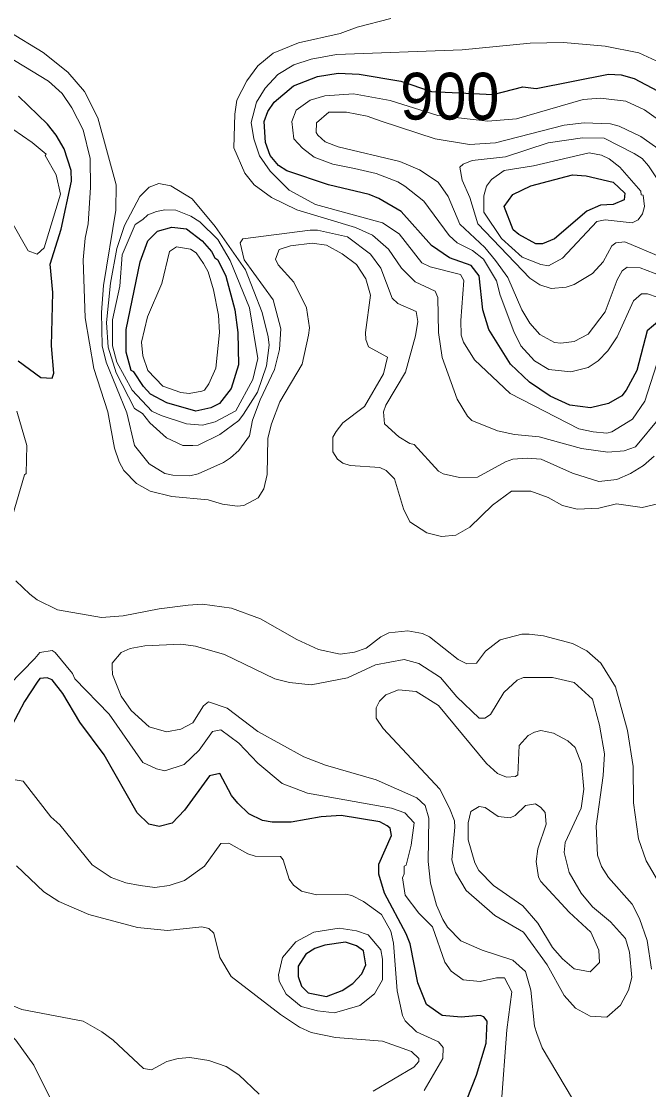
# Model space of a CAD drawing. Extents: x 423 to 448.8, y 7456.3 to 7484.
# Drawn here: x 425.114 to 426.187, y 7462.195 to 7464.022 of the extents above; entities that cross this region are included whole.
import ezdxf
from ezdxf.enums import TextEntityAlignment as Align

# ---------------------------------------------------------------- set-up
doc = ezdxf.new("R2010")
doc.units = 0
doc.header["$LTSCALE"] = 0.032
doc.layers.add('1', color=7, linetype='Continuous', lineweight=25)
doc.layers.add('2', color=7, linetype='Continuous', lineweight=13)
doc.layers.add('61', color=7, linetype='Continuous')

msp = doc.modelspace()

# ---------------------------------------------------------------- linework, layer by layer
at = {"layer": '1'}
for points in [[(426.206, 7463.5108), (426.1844, 7463.4923), (426.1666, 7463.425), (426.1488, 7463.3909), (426.1411, 7463.3816), (426.1186, 7463.3685), (426.0877, 7463.3608), (426.0521, 7463.3654), (426.0188, 7463.3809), (425.9833, 7463.4049), (425.9508, 7463.4358), (425.9136, 7463.4946), (425.9036, 7463.5286), (425.8974, 7463.5866), (425.8835, 7463.6044), (425.8464, 7463.6176), (425.8154, 7463.6384), (425.7636, 7463.6965), (425.7257, 7463.7189), (425.7087, 7463.7258), (425.6391, 7463.7421), (425.5679, 7463.7661), (425.554, 7463.7753), (425.5393, 7463.7924), (425.5315, 7463.8148), (425.5293, 7463.8504), (425.5354, 7463.8674), (425.5462, 7463.8836), (425.5795, 7463.9115), (425.6205, 7463.9277), (425.6561, 7463.9331), (425.6917, 7463.9316), (425.7629, 7463.9192), (425.8158, 7463.9015), (425.9213, 7463.8967), (425.972, 7463.9097), (425.9949, 7463.9068), (426.1186, 7463.9316), (426.1403, 7463.93), (426.162, 7463.9238), (426.2022, 7463.903)], [(425.1085, 7463.4412), (425.1472, 7463.4126), (425.1665, 7463.4118), (425.1696, 7463.4204), (425.1657, 7463.4668), (425.168, 7463.558), (425.1635, 7463.6064), (425.1821, 7463.6665), (425.1997, 7463.7483), (425.199, 7463.7669), (425.1874, 7463.804), (425.1735, 7463.8272), (425.1588, 7463.8457), (425.1092, 7463.8937)], [(425.3722, 7462.6507), (425.3498, 7462.6453), (425.332, 7462.6492), (425.3119, 7462.6686), (425.2554, 7462.7676), (425.2137, 7462.8232), (425.185, 7462.8727), (425.1665, 7462.8959), (425.158, 7462.899), (425.1456, 7462.8983), (425.141, 7462.8921), (425.1193, 7462.8588), (425.0752, 7462.7768)], [(425.8765, 7462.1797), (425.8928, 7462.2199), (425.909, 7462.2748), (425.9106, 7462.312), (425.9051, 7462.3197), (425.899, 7462.322), (425.8665, 7462.3189), (425.834, 7462.322), (425.8069, 7462.3406), (425.7922, 7462.3777), (425.7791, 7462.4443), (425.7721, 7462.4613), (425.735, 7462.5309), (425.7257, 7462.5634), (425.7257, 7462.5804), (425.7474, 7462.6299), (425.745, 7462.6422), (425.7396, 7462.6461), (425.7273, 7462.6531), (425.6608, 7462.6639), (425.6267, 7462.6616), (425.5757, 7462.6523), (425.5432, 7462.6523), (425.5262, 7462.6554), (425.5029, 7462.667), (425.4844, 7462.6848), (425.4735, 7462.6979), (425.4535, 7462.7358), (425.4356, 7462.7319), (425.3931, 7462.6731), (425.3722, 7462.6507)]]:
    msp.add_lwpolyline(points, dxfattribs=at)
for points in [[(425.9856, 7463.7405), (426.0568, 7463.7591), (426.08, 7463.7576), (426.1264, 7463.7467), (426.1465, 7463.7282), (426.1449, 7463.7166), (426.1264, 7463.7088), (426.1047, 7463.7073), (426.0815, 7463.6972), (426.0258, 7463.65), (426.0057, 7463.6415), (425.9941, 7463.6415), (425.9647, 7463.657), (425.9554, 7463.6655), (425.94, 7463.705), (425.9547, 7463.7258)], [(425.3305, 7463.6462), (425.3467, 7463.6632), (425.3715, 7463.6701), (425.3962, 7463.6671), (425.4233, 7463.6462), (425.4395, 7463.6284), (425.4449, 7463.6176), (425.4503, 7463.6137), (425.4635, 7463.5859), (425.479, 7463.5286), (425.4844, 7463.49), (425.4852, 7463.4343), (425.4728, 7463.3941), (425.4527, 7463.3685), (425.438, 7463.3608), (425.4125, 7463.3554), (425.3629, 7463.3693), (425.3351, 7463.384), (425.3227, 7463.3971), (425.3065, 7463.4227), (425.3018, 7463.425), (425.2933, 7463.4559), (425.2933, 7463.4946), (425.3173, 7463.6106)], [(425.663, 7462.3645), (425.6808, 7462.3769), (425.6963, 7462.3932), (425.7033, 7462.4086), (425.6994, 7462.4326), (425.687, 7462.4412), (425.6685, 7462.4473), (425.6329, 7462.4419), (425.6159, 7462.4365), (425.6004, 7462.4265), (425.5873, 7462.4063), (425.5872, 7462.3886), (425.5934, 7462.3723), (425.6043, 7462.3607), (425.636, 7462.3545)]]:
    msp.add_lwpolyline(points, close=True, dxfattribs=at)
at = {"layer": '2'}
for points in [[(425.7458, 7464.0267), (425.6886, 7464.012)], [(425.0914, 7464.0051), (425.151, 7463.9687), (425.1935, 7463.9347), (425.2222, 7463.9015), (425.2446, 7463.8566), (425.2763, 7463.7421), (425.2755, 7463.6988), (425.2546, 7463.5699), (425.2508, 7463.524), (425.2524, 7463.4668), (425.2593, 7463.4389), (425.2941, 7463.3523), (425.3073, 7463.2966), (425.3328, 7463.2649), (425.3591, 7463.2486), (425.373, 7463.2455), (425.4024, 7463.2447), (425.4163, 7463.2478), (425.4597, 7463.2672), (425.472, 7463.2757), (425.4859, 7463.2881), (425.5045, 7463.3128), (425.5095, 7463.3396), (425.5222, 7463.3748), (425.547, 7463.4265), (425.5555, 7463.4606), (425.5579, 7463.4962), (425.5445, 7463.5457), (425.495, 7463.6139), (425.4882, 7463.6431), (425.4929, 7463.6501), (425.6082, 7463.6647), (425.6205, 7463.6647), (425.6716, 7463.6531), (425.711, 7463.6238), (425.7288, 7463.5998), (425.7481, 7463.5487), (425.7582, 7463.5394), (425.7891, 7463.5255), (425.7922, 7463.5085), (425.7883, 7463.4838), (425.7713, 7463.4219), (425.7373, 7463.3654), (425.7334, 7463.3538), (425.735, 7463.3337), (425.7598, 7463.3113), (425.7783, 7463.2997), (425.786, 7463.2981), (425.8278, 7463.2525), (425.8356, 7463.2478)], [(425.6886, 7464.012), (425.6592, 7464.0012), (425.588, 7463.9849), (425.5447, 7463.9672), (425.5184, 7463.9455), (425.4999, 7463.92), (425.4828, 7463.8867), (425.479, 7463.8628), (425.4774, 7463.8055), (425.496, 7463.7622), (425.5122, 7463.7421), (425.5416, 7463.7204), (425.585, 7463.6996), (425.6855, 7463.6694), (425.7149, 7463.6562), (425.742, 7463.6323), (425.7644, 7463.5998), (425.7876, 7463.5766), (425.8216, 7463.5603), (425.8262, 7463.5495), (425.8278, 7463.49), (425.834, 7463.4467), (425.8595, 7463.3755), (425.8773, 7463.3469), (425.8843, 7463.3391), (425.9284, 7463.3213), (425.9578, 7463.3151), (425.9995, 7463.3113), (426.0722, 7463.2912), (426.1171, 7463.285), (426.1449, 7463.2873), (426.1643, 7463.2943), (426.206, 7463.3446)], [(426.2006, 7463.4343), (426.1805, 7463.3724), (426.1596, 7463.3414), (426.124, 7463.3198), (426.1155, 7463.3175), (426.0923, 7463.3198), (426.0676, 7463.3252), (425.95, 7463.3855), (425.8889, 7463.4428), (425.8703, 7463.473), (425.8665, 7463.4853), (425.8657, 7463.5101), (425.8711, 7463.5789), (425.8649, 7463.589), (425.8131, 7463.6021), (425.7992, 7463.609), (425.7605, 7463.6586), (425.7319, 7463.6771), (425.6174, 7463.7088), (425.5718, 7463.7328), (425.5393, 7463.7653), (425.5215, 7463.7916), (425.5115, 7463.821), (425.5068, 7463.8489), (425.5161, 7463.8836), (425.5308, 7463.9076), (425.5525, 7463.9308), (425.5803, 7463.9471), (425.6097, 7463.9571), (425.653, 7463.9649), (425.868, 7463.9733), (425.9841, 7463.9842), (426.0413, 7463.9857), (426.1125, 7463.9795), (426.1704, 7463.968), (426.2145, 7463.9471)], [(425.6113, 7463.6423), (425.5741, 7463.6377), (425.5548, 7463.6315), (425.5486, 7463.6153), (425.5532, 7463.6052), (425.5803, 7463.5758), (425.602, 7463.5317), (425.6066, 7463.4977), (425.6051, 7463.4853), (425.5942, 7463.4358), (425.5563, 7463.3709), (425.5416, 7463.3337), (425.5354, 7463.309), (425.5346, 7463.2471), (425.5285, 7463.2224), (425.5192, 7463.2068), (425.4944, 7463.1937), (425.4829, 7463.1929), (425.4581, 7463.196), (425.4334, 7463.2037), (425.3715, 7463.2092), (425.3344, 7463.2185), (425.3111, 7463.2316), (425.2895, 7463.254), (425.281, 7463.2687), (425.2732, 7463.292), (425.2662, 7463.3291), (425.2616, 7463.3538), (425.2377, 7463.4281), (425.223, 7463.5147), (425.2199, 7463.6137), (425.2229, 7463.6508), (425.2284, 7463.6756), (425.2322, 7463.7375), (425.2315, 7463.787), (425.2198, 7463.8365), (425.2005, 7463.8736), (425.1835, 7463.8984), (425.1603, 7463.9192), (425.0752, 7463.971)], [(426.2501, 7463.8202), (426.1797, 7463.8705), (426.148, 7463.8852), (426.1047, 7463.8906), (426.0753, 7463.8883), (425.9609, 7463.855), (425.9121, 7463.8512), (425.8265, 7463.861), (425.7447, 7463.8865), (425.6824, 7463.8976), (425.6329, 7463.8945), (425.6082, 7463.8867), (425.5842, 7463.8697), (425.5764, 7463.8504), (425.5803, 7463.821), (425.595, 7463.8047), (425.6151, 7463.7893), (425.6468, 7463.7777), (425.684, 7463.7699), (425.7211, 7463.7614), (425.7582, 7463.7475), (425.7698, 7463.7398), (425.8023, 7463.7142), (425.8456, 7463.6554), (425.8595, 7463.6431), (425.8858, 7463.63), (425.9044, 7463.6152), (425.9268, 7463.5781), (425.933, 7463.5534), (425.9562, 7463.4915), (425.9686, 7463.4668), (425.9918, 7463.4412), (426.0165, 7463.4265), (426.0537, 7463.4227), (426.0838, 7463.4296), (426.1008, 7463.4412), (426.117, 7463.4582), (426.1333, 7463.4822), (426.1612, 7463.5441), (426.1751, 7463.5557), (426.1852, 7463.5557), (426.2347, 7463.5387)], [(425.0659, 7463.8604), (425.1325, 7463.8148), (425.1564, 7463.7947), (425.1546, 7463.7923), (425.1734, 7463.7593), (425.1809, 7463.7263), (425.1531, 7463.6347), (425.1411, 7463.6235), (425.1253, 7463.6295), (425.0953, 7463.6825)], [(426.2084, 7463.8001), (426.1735, 7463.8248), (426.1364, 7463.8426), (426.1217, 7463.8465), (426.0769, 7463.8481), (426.0428, 7463.8442), (425.9253, 7463.814), (425.8804, 7463.8109), (425.8216, 7463.821), (425.7296, 7463.8511), (425.7056, 7463.8597), (425.67, 7463.8666), (425.6398, 7463.8666), (425.6189, 7463.8481), (425.6182, 7463.8318), (425.6213, 7463.8272), (425.6337, 7463.8156), (425.6561, 7463.807), (425.7613, 7463.7823), (425.7953, 7463.7676), (425.827, 7463.7467), (425.8441, 7463.722), (425.8642, 7463.6748), (425.9067, 7463.6353), (425.9252, 7463.6129), (425.9461, 7463.5835), (425.9701, 7463.5286), (425.984, 7463.5054), (426.001, 7463.4861), (426.0258, 7463.4729), (426.0367, 7463.4714), (426.0599, 7463.4745), (426.0838, 7463.4868), (426.1124, 7463.5248), (426.1333, 7463.5797), (426.1418, 7463.5951), (426.1503, 7463.6013), (426.1728, 7463.6005), (426.2084, 7463.5866)], [(426.2084, 7463.6183), (426.1465, 7463.6446), (426.131, 7463.6431), (426.124, 7463.6377), (426.1093, 7463.6106), (426.0908, 7463.5905), (426.0599, 7463.5719), (426.0459, 7463.5673), (426.0204, 7463.565), (426.0011, 7463.5712), (425.984, 7463.5827), (425.8951, 7463.6756), (425.8812, 7463.7205), (425.868, 7463.7499), (425.8642, 7463.7723), (425.8696, 7463.7776), (425.8851, 7463.7838), (425.9423, 7463.79), (426.015, 7463.814), (426.0738, 7463.8225), (426.1109, 7463.8218), (426.162, 7463.7955), (426.1759, 7463.787), (426.1867, 7463.7746), (426.2385, 7463.6973)], [(426.2122, 7463.1991), (426.1759, 7463.1906), (426.1318, 7463.1968), (426.1016, 7463.1891), (426.0645, 7463.1875), (426.0397, 7463.1937), (426.015, 7463.2076), (425.9856, 7463.2185), (425.9523, 7463.2185), (425.9198, 7463.1945), (425.8812, 7463.1566), (425.8572, 7463.1434), (425.8325, 7463.1411), (425.8077, 7463.1473), (425.7783, 7463.1659), (425.7675, 7463.1883), (425.752, 7463.2394), (425.7381, 7463.254), (425.7273, 7463.2587), (425.6762, 7463.2625), (425.6638, 7463.2664), (425.6546, 7463.2734), (425.6468, 7463.2858), (425.6468, 7463.3105), (425.6522, 7463.3206), (425.6638, 7463.3352), (425.7009, 7463.3631), (425.7334, 7463.4188), (425.7404, 7463.4474), (425.7079, 7463.4652), (425.7033, 7463.4776), (425.7025, 7463.49), (425.711, 7463.5534), (425.7033, 7463.5812), (425.687, 7463.606), (425.663, 7463.6245), (425.636, 7463.6392), (425.6113, 7463.6423)], [(425.1062, 7463.3554), (425.1232, 7463.2966), (425.1224, 7463.2486), (425.1193, 7463.2463), (425.0922, 7463.1527)], [(425.8356, 7463.2478), (425.8634, 7463.2417), (425.8943, 7463.2424), (425.9423, 7463.2687), (425.9547, 7463.2734), (425.9794, 7463.2749), (426.0034, 7463.2734), (426.0568, 7463.2494), (426.1016, 7463.2347), (426.1326, 7463.2386), (426.1558, 7463.2486), (426.1782, 7463.2625), (426.1967, 7463.278)], [(425.1046, 7463.0653), (425.1286, 7463.0421), (425.1409, 7463.0328), (425.1758, 7463.0158), (425.2508, 7463.0026), (425.2879, 7463.005), (425.3498, 7463.0174), (425.3993, 7463.0235), (425.4241, 7463.0251), (425.4736, 7463.0182), (425.5231, 7463.0003), (425.585, 7462.9648), (425.6221, 7462.9477), (425.6592, 7462.94), (425.684, 7462.9431), (425.704, 7462.9501), (425.7288, 7462.9694), (425.7427, 7462.9764), (425.7752, 7462.9794), (425.8, 7462.9748), (425.8124, 7462.9694), (425.8611, 7462.9307), (425.8758, 7462.923), (425.8927, 7462.9245), (425.9082, 7462.9447), (425.933, 7462.964), (425.9701, 7462.974), (425.9825, 7462.9741), (426.0073, 7462.9709), (426.0568, 7462.9578), (426.0815, 7462.9454), (426.1055, 7462.9245), (426.1302, 7462.8836), (426.1511, 7462.8093), (426.1604, 7462.7474), (426.1612, 7462.6856), (426.1697, 7462.6237), (426.1828, 7462.5866), (426.2215, 7462.5201)], [(426.1921, 7462.4009), (426.1844, 7462.4504), (426.1712, 7462.4876), (426.1588, 7462.5123), (426.1186, 7462.5579), (426.1063, 7462.5765), (426.0993, 7462.5958), (426.097, 7462.6454), (426.1094, 7462.732), (426.1116, 7462.7691), (426.1032, 7462.8186), (426.0908, 7462.8627), (426.0599, 7462.8913), (426.0227, 7462.8998), (425.9732, 7462.8998), (425.9624, 7462.8951), (425.9392, 7462.8743), (425.9167, 7462.8364), (425.9067, 7462.8302), (425.8974, 7462.8302), (425.8588, 7462.8665), (425.8309, 7462.8998), (425.7938, 7462.9238), (425.769, 7462.9307), (425.7195, 7462.9214), (425.6716, 7462.899), (425.6097, 7462.8874), (425.5726, 7462.8913), (425.5478, 7462.8975), (425.4612, 7462.9393), (425.4117, 7462.9532), (425.3869, 7462.957), (425.3251, 7462.9539), (425.3003, 7462.9493), (425.2848, 7462.9423), (425.2694, 7462.9245), (425.2694, 7462.9176), (425.2701, 7462.9052), (425.2848, 7462.8681), (425.3018, 7462.8433), (425.3328, 7462.8155), (425.3622, 7462.807), (425.3869, 7462.8116), (425.4071, 7462.8224), (425.4256, 7462.8511), (425.4341, 7462.858), (425.4658, 7462.8472), (425.5184, 7462.8077), (425.5973, 7462.7644), (425.6345, 7462.7497), (425.7211, 7462.725), (425.7907, 7462.6941), (425.8046, 7462.6809), (425.8108, 7462.6593), (425.81, 7462.585), (425.8139, 7462.5479), (425.8239, 7462.5108), (425.8348, 7462.486), (425.8432, 7462.4728), (425.8657, 7462.4496), (425.9021, 7462.4334), (425.9546, 7462.4164), (425.9763, 7462.397), (425.9856, 7462.3654), (425.9918, 7462.3035), (425.9956, 7462.2911), (426.0049, 7462.2664), (426.0567, 7462.1797)], [(425.9346, 7462.1674), (425.9446, 7462.2973), (425.9531, 7462.3622), (425.9407, 7462.3862), (425.9268, 7462.3862), (425.899, 7462.38), (425.8696, 7462.3831), (425.8494, 7462.3978), (425.8386, 7462.4133), (425.817, 7462.4736), (425.7938, 7462.4968), (425.7705, 7462.5278), (425.7659, 7462.5572), (425.769, 7462.5641), (425.769, 7462.5772), (425.7721, 7462.5788), (425.7806, 7462.6129), (425.786, 7462.6515), (425.7698, 7462.6685), (425.7474, 7462.6763), (425.6035, 7462.7018), (425.5602, 7462.7188), (425.5184, 7462.7536), (425.4859, 7462.7877), (425.455, 7462.8101), (425.4411, 7462.8077), (425.4179, 7462.7753), (425.3923, 7462.7513), (425.3591, 7462.7405), (425.3452, 7462.7435), (425.3219, 7462.7544), (425.264, 7462.8372), (425.2052, 7462.8975), (425.2013, 7462.9067), (425.1719, 7462.9423), (425.1665, 7462.9462), (425.1456, 7462.9423), (425.1371, 7462.9323), (425.093, 7462.8874)], [(425.1031, 7462.725), (425.117, 7462.7227), (425.1642, 7462.6616), (425.1797, 7462.6477), (425.2353, 7462.5796), (425.2678, 7462.5579), (425.2926, 7462.5486), (425.3173, 7462.544), (425.3421, 7462.5409), (425.3668, 7462.544), (425.3931, 7462.5525), (425.4272, 7462.5772), (425.455, 7462.616), (425.4689, 7462.6167), (425.5014, 7462.5981), (425.5138, 7462.5943), (425.5571, 7462.5935)], [(425.5571, 7462.5935), (425.5618, 7462.5881), (425.5718, 7462.5548), (425.5795, 7462.5448), (425.5934, 7462.5347), (425.619, 7462.5285), (425.6685, 7462.5293), (425.6793, 7462.527), (425.6994, 7462.5169), (425.7303, 7462.4945), (425.7458, 7462.4659), (425.7505, 7462.4458), (425.7567, 7462.3638), (425.7659, 7462.322), (425.7705, 7462.3128), (425.7899, 7462.2942), (425.8278, 7462.2771), (425.8356, 7462.2671), (425.8348, 7462.2485), (425.803, 7462.1936)], [(425.1054, 7462.578), (425.1526, 7462.5332), (425.1781, 7462.517), (425.2292, 7462.4945), (425.3127, 7462.4721), (425.3637, 7462.4674), (425.4225, 7462.4736), (425.4349, 7462.4705), (425.4434, 7462.4628), (425.4535, 7462.421), (425.4728, 7462.3885), (425.5571, 7462.3236), (425.5895, 7462.3019), (425.6097, 7462.2926), (425.6515, 7462.2841), (425.7319, 7462.2779), (425.7814, 7462.2602)], [(425.5207, 7462.1875), (425.486, 7462.2207), (425.4643, 7462.2346), (425.4349, 7462.2447), (425.4024, 7462.2501), (425.3823, 7462.2485), (425.363, 7462.2431), (425.3366, 7462.2292), (425.3227, 7462.2315), (425.2709, 7462.2795), (425.2516, 7462.2942), (425.2199, 7462.312), (425.1147, 7462.3321), (425.0327, 7462.3661)], [(425.1673, 7462.1727), (425.1355, 7462.237), (425.1046, 7462.2795), (425.0822, 7462.3019), (425.0513, 7462.3189), (425.0203, 7462.3236), (424.9987, 7462.322), (424.977, 7462.3159), (424.9492, 7462.298), (424.929, 7462.2764), (424.9174, 7462.2555), (424.9105, 7462.2246), (424.9136, 7462.1774)], [(425.7814, 7462.2602), (425.7937, 7462.2485), (425.7937, 7462.2431), (425.7853, 7462.2338), (425.7156, 7462.1928)]]:
    msp.add_lwpolyline(points, dxfattribs=at)
for points in [[(426.0397, 7463.6168), (426.0985, 7463.6795), (426.1125, 7463.6825), (426.1589, 7463.6771), (426.1689, 7463.6825), (426.1766, 7463.6926), (426.1797, 7463.705), (426.1774, 7463.7243), (426.1743, 7463.7251), (426.1735, 7463.7313), (426.138, 7463.7722), (426.1194, 7463.7869), (426.1063, 7463.7931), (426.0854, 7463.797), (425.9902, 7463.7746), (425.9399, 7463.7669), (425.9183, 7463.7514), (425.9098, 7463.7398), (425.9051, 7463.7236), (425.9051, 7463.6957), (425.9355, 7463.6503), (425.9708, 7463.6188), (426.0026, 7463.6059), (426.0158, 7463.6037)], [(425.4071, 7463.2966), (425.4163, 7463.2973), (425.4535, 7463.3151), (425.4859, 7463.3391), (425.4937, 7463.3499), (425.5177, 7463.3875), (425.5335, 7463.4325), (425.5377, 7463.4683), (425.5362, 7463.4822), (425.5261, 7463.524), (425.4972, 7463.5967), (425.4454, 7463.6709), (425.4063, 7463.7181), (425.3699, 7463.7405), (425.349, 7463.7444), (425.3328, 7463.7382), (425.3165, 7463.722), (425.2903, 7463.6725), (425.2775, 7463.6336), (425.2663, 7463.5743), (425.2595, 7463.5068), (425.2625, 7463.4648), (425.276, 7463.4205), (425.3075, 7463.3597), (425.3212, 7463.3515), (425.3335, 7463.3353), (425.3622, 7463.3097), (425.39, 7463.2966)], [(425.3034, 7463.3909), (425.2771, 7463.4389), (425.2701, 7463.4668), (425.2701, 7463.5116), (425.2825, 7463.5689), (425.2864, 7463.6227), (425.3089, 7463.6744), (425.322, 7463.6831), (425.3305, 7463.691), (425.3452, 7463.6965), (425.3591, 7463.6996), (425.3784, 7463.6988), (425.404, 7463.6887), (425.4194, 7463.6787), (425.4502, 7463.6488), (425.4712, 7463.6128), (425.5045, 7463.5317), (425.5184, 7463.4451), (425.5101, 7463.4092), (425.4808, 7463.3559), (425.4457, 7463.3368), (425.4241, 7463.3314), (425.3962, 7463.3337), (425.3529, 7463.3476), (425.3374, 7463.3554)], [(425.4225, 7463.3894), (425.4272, 7463.391), (425.4349, 7463.4018), (425.4465, 7463.4288), (425.4527, 7463.49), (425.4511, 7463.5194), (425.4426, 7463.5627), (425.4334, 7463.5936), (425.4256, 7463.6075), (425.4132, 7463.6261), (425.4032, 7463.6322), (425.3792, 7463.6361), (425.3676, 7463.6284), (425.3545, 7463.5735), (425.3297, 7463.5163), (425.3196, 7463.473), (425.322, 7463.4497), (425.3305, 7463.425), (425.356, 7463.3979), (425.3869, 7463.3871), (425.4009, 7463.3855)], [(426.1391, 7462.3398), (426.1526, 7462.3654), (426.1581, 7462.387), (426.1542, 7462.4303), (426.1472, 7462.4535), (426.1217, 7462.4821), (426.0908, 7462.5076), (426.0714, 7462.5309), (426.0513, 7462.5665), (426.0428, 7462.6005), (426.0443, 7462.6175), (426.0714, 7462.6763), (426.0761, 7462.7088), (426.0722, 7462.7521), (426.0614, 7462.7799), (426.049, 7462.7915), (426.0243, 7462.8047), (426.0026, 7462.8093), (425.9918, 7462.8062), (425.981, 7462.8008), (425.9655, 7462.7838), (425.9632, 7462.7335), (425.9593, 7462.7304), (425.9438, 7462.7296), (425.9284, 7462.7358), (425.9098, 7462.7528), (425.8278, 7462.8518), (425.7891, 7462.8758), (425.759, 7462.8789), (425.7373, 7462.8704), (425.7265, 7462.8596), (425.7211, 7462.848), (425.7211, 7462.8302), (425.7327, 7462.8124), (425.8301, 7462.7088), (425.8464, 7462.6763), (425.8549, 7462.6546), (425.8557, 7462.6438), (425.8502, 7462.5881), (425.8564, 7462.5665), (425.875, 7462.5355), (425.9237, 7462.4929), (425.9732, 7462.4644), (426.0134, 7462.4087), (426.0428, 7462.3561), (426.0622, 7462.3344), (426.0869, 7462.3205), (426.1155, 7462.3189)], [(425.9948, 7462.585), (425.9972, 7462.6067), (426.0119, 7462.6492), (426.0098, 7462.6691), (426.0026, 7462.6778), (425.9933, 7462.684), (425.9763, 7462.6809), (425.9585, 7462.6639), (425.95, 7462.66), (425.9299, 7462.6623), (425.9075, 7462.6778), (425.8974, 7462.6794), (425.8827, 7462.6709), (425.8781, 7462.6515), (425.8781, 7462.6221), (425.8897, 7462.5827), (425.8966, 7462.5696), (425.9214, 7462.544), (425.9716, 7462.5092), (425.9972, 7462.4798), (426.0227, 7462.438), (426.0397, 7462.4187), (426.0599, 7462.4017), (426.0869, 7462.3963), (426.1032, 7462.4125), (426.1016, 7462.4334), (426.0884, 7462.4644), (426.0513, 7462.4984), (426.0026, 7462.551), (425.9987, 7462.5587)], [(425.6143, 7462.4643), (425.6577, 7462.4713), (425.6871, 7462.4666), (425.7071, 7462.4597), (425.7288, 7462.4342), (425.7319, 7462.418), (425.7319, 7462.3831), (425.7179, 7462.3592), (425.6932, 7462.339), (425.6499, 7462.3266), (425.6205, 7462.3297), (425.5927, 7462.3375), (425.5671, 7462.3584), (425.5548, 7462.3808), (425.554, 7462.3917), (425.5609, 7462.421), (425.5834, 7462.4481)]]:
    msp.add_lwpolyline(points, close=True, dxfattribs=at)

# ---------------------------------------------------------------- texts
at = {"layer": '61', "width": 0.95}
msp.add_text('900', height=0.08, dxfattribs=at).set_placement((425.8469, 7463.8538), align=Align.CENTER)

doc.saveas('drawing.dxf')
